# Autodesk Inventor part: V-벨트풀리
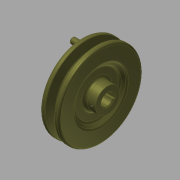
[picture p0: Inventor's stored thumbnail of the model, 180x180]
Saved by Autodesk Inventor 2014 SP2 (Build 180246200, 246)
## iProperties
Company: 한국ATC센터
Created: 2015-12
Part Number: V-벨트풀리
Document SubType Name: Modeling
Designer: mdu
Density: 7.25 g/cm^3
Mass: 596.621 g
Surface Area: 212.231 cm^2
Volume: 82.2926 cm^3
Material: 주철
Appearance: 티타늄
Author: mdu
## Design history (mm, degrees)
sketch "스케치1"
  geometry: L1 (-13, 0)-(13, 0); L2 (-13, 0)-(-13, 12.5); L3 (-13, 12.5)-(-9, 12.5); L4 (-9, 12.5)-(-9, 23); L5 (-9, 23)-(-13, 27); L6 (-13, 27)-(-13, 42.7); L7 (-13, 42.7)-(-8.325, 42.7); L8 (-8.325, 42.7)-(-5.574, 33.7); L9 (-5.574, 33.7)-(-1.426, 33.7); L10 (-1.426, 33.7)-(1.325, 42.7); L11 (1.325, 42.7)-(6, 42.7); L12 (6, 42.7)-(6, 27); L13 (6, 27)-(2, 23); L14 (2, 23)-(2, 12.5); L15 (2, 12.5)-(13, 12.5); L16 (13, 12.5)-(13, 0); L17 (-7.5, 40)-(0.5, 40); 2 further points
  constraints: 34 end point, 6 parallel, 5 collinear, 5 equal length, 4 perpendicular, 2 point on line, 1 coincident, 1 horizontal, 1 midpoint
  dimensions: "d0" = 26 distance of L1.start L1.end; "d1" = 2.7 distance between parallel lines of L7 L17; "d2" = 6.3 distance between parallel lines of L9 L17; "d3" = 8 distance of L17.start L17.end; "d4" = 34 deg angle of L10 L8; "d5" = 19 distance between parallel lines of L12 L6; "d7" = 25 diameter of L15 L1; "d8" = 46 diameter of L13.end L1; "d9" = 54 diameter of L12.end L1; "d10" = 4 distance between parallel lines of L2 L4; "d11" = 80 diameter of L17 L1
revolve "회전1" sketch "스케치1" stored, may be unused: angle "d12" = 90 deg
sketch "스케치2"
  geometry: L1 (-2, 5.657)-(-2, 7.8); L2 (-2, 7.8)-(2, 7.8); L3 (2, 7.8)-(2, 5.657); A1 r 6 centre (0, 0) between (-2, 5.657) and (2, 5.657); 1 further point
  constraints: 6 end point, 2 parallel, 2 point on circle, 1 centre point, 1 coincident, 1 perpendicular, 1 vertical
  dimensions: "d13" = 12 diameter of A1; "d14" = 13.8 dimension on A1 L2; "d15" = 4 distance of L1.end L2.end
extrude "돌출1" cut sketch "스케치2" stored distance "d16" = 10; taper "d17" = 0 deg
node "작업 평면1"
sketch "스케치3"
  geometry: L1 (-5.5, 12.5)-(-5.5, -12.5) reference; L2 (20.5, 27)-(20.5, -27) reference; 3 further points
  constraints: 1 horizontal alignment, 1 midpoint
  dimensions: "d18" = 4 distance from line of point (-1.5, 0) L1; "d33" = 22 distance from line of point (-1.5, 0) L2 (derived)
hole "구멍1" sketch "스케치3" at (-1.5, 0) diameter "d19" = 2.459; stored, may be unused: countersink angle "d23" = 90 deg, drill point angle "d25" = 118 deg; dims "d20" = 6, "d21" = 4, "d22" = 2, "d24" = 8
fillet "모깎기1" dims "d26" = 2, "d27" = 0.5, "d28" = 1, "d29" = 3
chamfer "모따기1" distance "d30" = 1; stored, may be unused: second distance "d31" = 2, angle "d32" = 45 deg
sketch "스케치4" dims "d35" = 70
  geometry: C1 r 3 at (35, 0); 2 further points
  constraints: 2 horizontal alignment, 1 centre point, 1 coincident, 2 other
  dimensions: "d34" = 6 diameter of C1
extrude "돌출2" join sketch "스케치4" distance "d36" = 10; taper "d37" = 0 deg
fillet "모깎기2" dims "d38" = 0.5, "d39" = 1
node "솔리드1"
